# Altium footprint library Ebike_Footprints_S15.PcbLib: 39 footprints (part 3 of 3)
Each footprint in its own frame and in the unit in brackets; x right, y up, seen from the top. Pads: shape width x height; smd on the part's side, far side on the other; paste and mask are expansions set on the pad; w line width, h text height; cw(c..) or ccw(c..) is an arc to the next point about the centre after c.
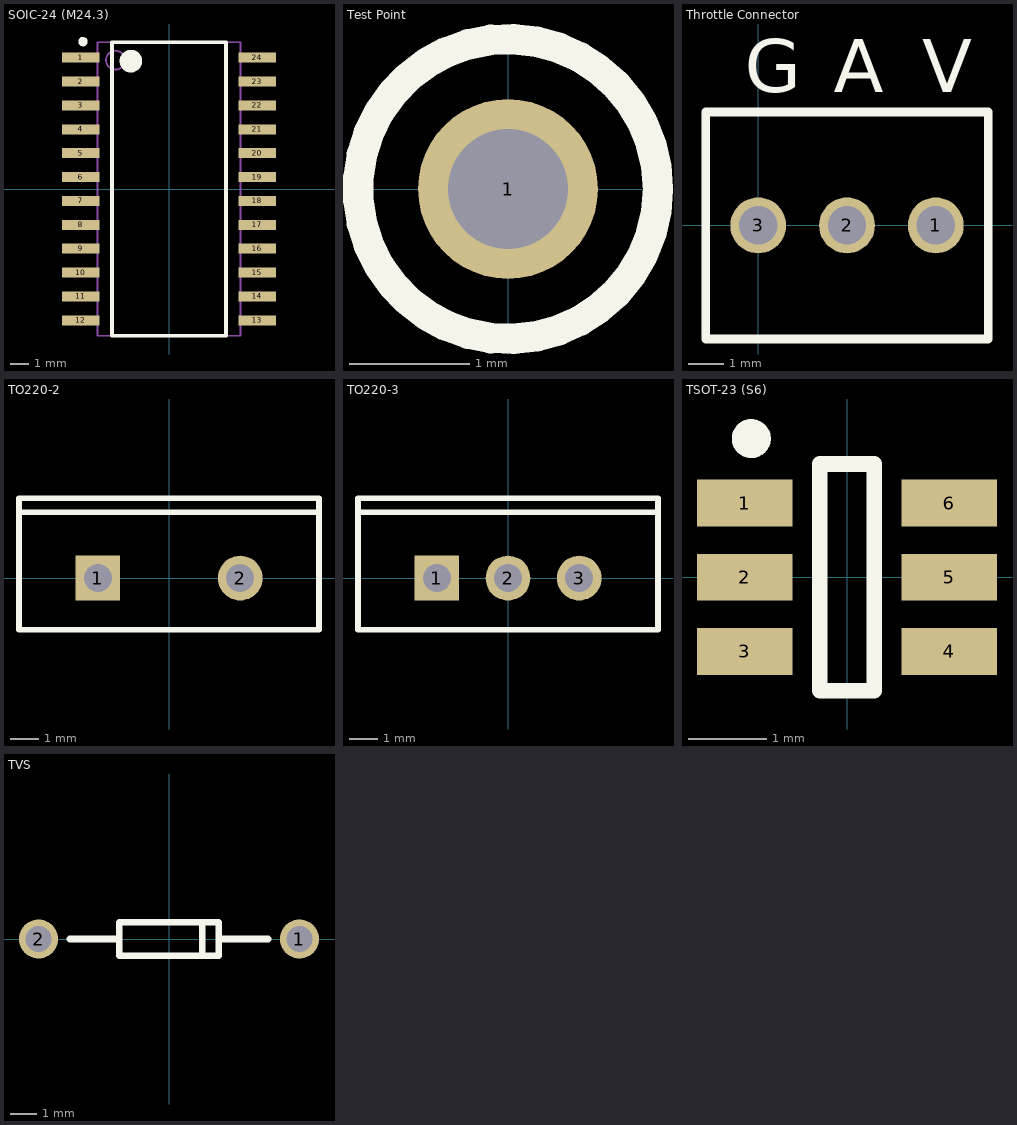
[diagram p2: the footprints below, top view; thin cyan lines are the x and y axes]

## SOIC-24 (M24.3) [mil] "HIP4086 3-Phase Motor Drive SMD"
height 104.33
pads (24):
  rect 77.99x20.98 smd: 1(-184.51,275) 2(-184.51,225) 3(-184.51,175) 4(-184.51,125) 5(-184.51,75) 6(-184.51,25) 7(-184.51,-25) 8(-184.51,-75) 9(-184.51,-125) 10(-184.51,-175) 11(-184.51,-225) 12(-184.51,-275) 13(184.51,-275) 14(184.51,-225) 15(184.51,-175) 16(184.51,-125) 17(184.51,-75) 18(184.51,-25) 19(184.51,25) 20(184.51,75) 21(184.51,125) 22(184.51,175) 23(184.51,225) 24(184.51,275)
Top Overlay:
  circle w9.84: c-180.12,308.46 r4.92
  circle w23.62: c-79.72,267.72 r11.81
  lines w7.87: -119.09,-307.09 -119.09,307.09 119.09,307.09 119.09,-307.09 -119.09,-307.09
Mechanical 13:
  circle w3.94: c-112.2,269.69 r19.68
  lines w3.94: -149.61,-307.09 -149.61,307.09 149.61,307.09 149.61,-307.09 -149.61,-307.09
3D body: height 104.33, standoff 3.94, extent -149.61,-307.09 149.61,307.09

## Test Point [mm] "Keystone 500(0-4)"
pads (1):
  round 1.5 hole 1: 1(0,0)
Top Overlay:
  circle w0.254: c0,0 r1.25
3D body: height 3.05, standoff -4.57, extent -1.27,-1.27 1.27,1.27

## Throttle Connector [mm] "Phoenix 3-terminal Block Screw connector"
pads (3):
  round 1.6 hole 1.1: 1(5.08,0) 2(2.54,0) 3(0,0)
Top Overlay:
  lines w0.254: -1.5,-3.25 6.58,-3.25 6.58,3.25 -1.5,3.25 -1.5,-3.25
  text "A" at 2.159,3.81 h1.52
  text "V" at 4.699,3.81 h1.52
  text "G" at -0.381,3.81 h1.52

## TO220-2 [mm]
pads (2):
  rect 1.6x1.6 hole 1: 1(-2.54,0)
  round 1.6 hole 1: 2(2.54,0)
Top Overlay:
  lines w0.2: -5.35,2.35 5.35,2.35 ; -5.35,-1.85 5.35,-1.85 5.35,2.85 -5.35,2.85 -5.35,-1.85
3D body: height 19.11, standoff -3, extent -5.969,-1.905 5.915,2.495

## TO220-3 [mm]
pads (3):
  rect 1.6x1.6 hole 1: 1(-2.54,0)
  round 1.6 hole 1: 2(0,0) 3(2.54,0)
Top Overlay:
  lines w0.2: -5.35,2.35 5.35,2.35 ; -5.35,-1.85 5.35,-1.85 5.35,2.85 -5.35,2.85 -5.35,-1.85
3D body: height 19.11, standoff -3, extent -5.969,-1.692 5.915,2.708

## TSOT-23 (S6) [mm] "LTC6992, TSOT-23 package"
height 1
pads (6):
  rect 1.22x0.6 smd: 1(-1.31,0.95) 2(-1.31,0) 3(-1.31,-0.95) 4(1.31,-0.95) 5(1.31,0) 6(1.31,0.95)
Top Overlay:
  circle w0.25: c-1.225,1.775 r0.125
  lines w0.2: -0.35,-1.45 -0.35,1.45 0.35,1.45 0.35,-1.45 -0.35,-1.45
3D body: height 1, standoff 0.01, extent -0.85,-1.45 0.85,1.45

## TVS [mm] "P6KE TVS Diode Axial"
pads (2):
  round 1.5 hole 1: 1(5,0) 2(-5,0)
Top Overlay:
  lines w0.254: -3.81,0 -1.905,0 ; 1.27,-0.635 1.27,0.635 ; 3.81,0 1.905,0 ; -1.905,0 -1.905,-0.635 1.905,-0.635 1.905,0 ; -1.905,0 -1.905,0.635 1.905,0.635 1.905,0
